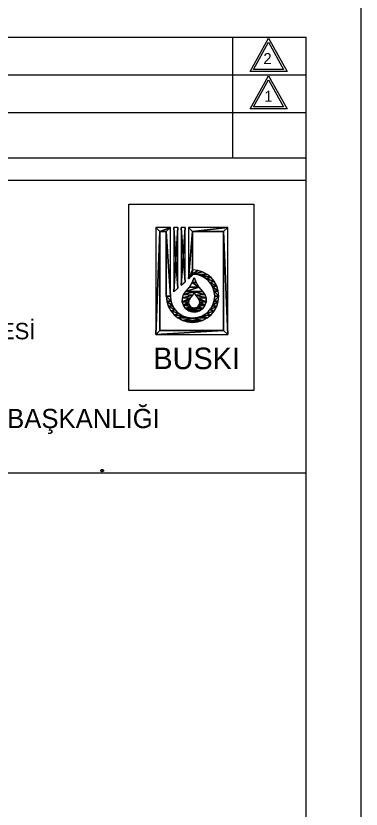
# Model space of a CAD drawing. Extents: x -10 to 1145, y -10 to 821.
# Drawn here: x 1082.1 to 1145, y 138.4 to 283.1 of the extents above; entities that cross this region are included whole.
import ezdxf

# ---------------------------------------------------------------- set-up
doc = ezdxf.new("R2010")
doc.units = 0
for name, color, linetype in [('Level 1', 7, 'Continuous'), ('Level 20', 7, 'Continuous'), ('Level 21', 7, 'Continuous'), ('Level 51', 7, 'Continuous'), ('Level 6', 7, 'Continuous'), ('Level 7', 7, 'Continuous'), ('Level 8', 7, 'Continuous')]:
    doc.layers.add(name, color=color, linetype=linetype)

msp = doc.modelspace()

# ---------------------------------------------------------------- linework, layer by layer
at = {"layer": 'Level 1'}
msp.add_lwpolyline([(1097.86, 200.4), (1097.9, 200.4), (1097.99, 200.36), (1098.03, 200.27), (1098.03, 200.1), (1097.94, 200.02), (1097.82, 199.97), (1097.69, 200.02), (1097.6, 200.1), (1097.6, 200.27), (1097.65, 200.36), (1097.73, 200.4), (1097.86, 200.4), (1097.99, 200.27), (1097.99, 200.14), (1097.9, 200.06), (1097.82, 199.97), (1097.9, 200.1), (1097.9, 200.31), (1097.86, 200.4)], dxfattribs=at)
msp.add_lwpolyline([(1097.86, 200.4), (1097.9, 200.4), (1097.99, 200.36), (1098.03, 200.27), (1098.03, 200.1), (1097.94, 200.02), (1097.82, 199.97), (1097.69, 200.02), (1097.6, 200.1), (1097.6, 200.27), (1097.65, 200.36), (1097.73, 200.4), (1097.86, 200.4), (1097.99, 200.27), (1097.99, 200.14), (1097.9, 200.06), (1097.82, 199.97), (1097.9, 200.1), (1097.9, 200.31), (1097.86, 200.4)], dxfattribs=at)
msp.add_lwpolyline([(1097.86, 200.4), (1097.9, 200.4), (1097.99, 200.36), (1098.03, 200.27), (1098.03, 200.1), (1097.94, 200.02), (1097.82, 199.97), (1097.69, 200.02), (1097.6, 200.1), (1097.6, 200.27), (1097.65, 200.36), (1097.73, 200.4), (1097.86, 200.4), (1097.99, 200.27), (1097.99, 200.14), (1097.9, 200.06), (1097.82, 199.97), (1097.9, 200.1), (1097.9, 200.31), (1097.86, 200.4)], dxfattribs=at)
msp.add_lwpolyline([(1097.86, 200.4), (1097.9, 200.4), (1097.99, 200.36), (1098.03, 200.27), (1098.03, 200.1), (1097.94, 200.02), (1097.82, 199.97), (1097.69, 200.02), (1097.6, 200.1), (1097.6, 200.27), (1097.65, 200.36), (1097.73, 200.4), (1097.86, 200.4), (1097.99, 200.27), (1097.99, 200.14), (1097.9, 200.06), (1097.82, 199.97), (1097.9, 200.1), (1097.9, 200.31), (1097.86, 200.4)], dxfattribs=at)
at = {"layer": 'Level 51'}
msp.add_lwpolyline([(-10, -10), (1145, -10), (1145, 821), (-10, 821)], close=True, dxfattribs=at)
at = {"layer": 'Level 6'}
for p, q in [((967.03, 279.24), (1135, 279.24)), ((967.03, 279.24), (1135, 279.24)), ((967.03, 279.24), (1135, 279.24)), ((967.03, 279.24), (1135, 279.24)), ((970.15, 279.24), (1131.87, 279.24)), ((970.15, 279.24), (1131.87, 279.24)), ((970.15, 279.24), (1131.87, 279.24)), ((970.15, 279.24), (1131.87, 279.24)), ((970.15, 279.24), (1131.87, 279.24)), ((970.15, 279.24), (1131.87, 279.24)), ((970.15, 279.24), (1131.87, 279.24)), ((970.15, 279.24), (1131.87, 279.24)), ((1121.62, 257.23), (1121.62, 279.24)), ((1121.62, 257.23), (1121.62, 279.24)), ((1121.62, 257.23), (1121.62, 279.24)), ((1121.62, 257.23), (1121.62, 279.24)), ((1135, 255.72), (1135, 279.24)), ((1135, 255.72), (1135, 279.24)), ((1135, 255.72), (1135, 279.24)), ((1135, 255.72), (1135, 279.24)), ((1135, 255.72), (1135, 279.24)), ((1135, 255.72), (1135, 279.24)), ((1135, 255.72), (1135, 279.24)), ((1135, 255.72), (1135, 279.24)), ((967.03, 272.38), (1135, 272.38)), ((967.03, 272.38), (1135, 272.38)), ((967.03, 272.38), (1135, 272.38)), ((967.03, 272.38), (1135, 272.38)), ((967.03, 265.52), (1135, 265.52)), ((967.03, 265.52), (1135, 265.52)), ((967.03, 265.52), (1135, 265.52)), ((967.03, 265.52), (1135, 265.52)), ((1135, 0), (1135, 262.93)), ((1135, 0), (1135, 262.93)), ((1135, 0), (1135, 262.93)), ((1135, 0), (1135, 262.93)), ((967.03, 257.23), (1135, 257.23)), ((967.03, 257.23), (1135, 257.23)), ((967.03, 257.23), (1135, 257.23)), ((967.03, 257.23), (1135, 257.23)), ((967.03, 253.14), (1135, 253.14)), ((967.03, 253.14), (1135, 253.14)), ((967.03, 253.14), (1135, 253.14)), ((967.03, 253.14), (1135, 253.14)), ((967.03, 199.78), (1135, 199.78)), ((967.03, 199.78), (1135, 199.78)), ((967.03, 199.78), (1135, 199.78)), ((967.03, 199.78), (1135, 199.78))]:
    msp.add_line(p, q, dxfattribs=at)
at = {"layer": 'Level 7'}
for points in [[(1124.76, 273), (1128.13, 279.05), (1131.5, 273)], [(1124.76, 273), (1128.13, 279.05), (1131.5, 273)], [(1124.76, 273), (1128.13, 279.05), (1131.5, 273)], [(1124.76, 273), (1128.13, 279.05), (1131.5, 273)], [(1125.38, 273.37), (1128.13, 278.3), (1130.88, 273.37)], [(1125.38, 273.37), (1128.13, 278.3), (1130.88, 273.37)], [(1125.38, 273.37), (1128.13, 278.3), (1130.88, 273.37)], [(1125.38, 273.37), (1128.13, 278.3), (1130.88, 273.37)], [(1124.76, 266.14), (1128.13, 272.19), (1131.5, 266.14)], [(1124.76, 266.14), (1128.13, 272.19), (1131.5, 266.14)], [(1124.76, 266.14), (1128.13, 272.19), (1131.5, 266.14)], [(1124.76, 266.14), (1128.13, 272.19), (1131.5, 266.14)], [(1125.38, 266.51), (1128.13, 271.44), (1130.88, 266.51)], [(1125.38, 266.51), (1128.13, 271.44), (1130.88, 266.51)], [(1125.38, 266.51), (1128.13, 271.44), (1130.88, 266.51)], [(1125.38, 266.51), (1128.13, 271.44), (1130.88, 266.51)]]:
    msp.add_lwpolyline(points, close=True, dxfattribs=at)
at = {"layer": 'Level 8'}
for points in [[(1102.65, 248.8), (1125.44, 248.8), (1125.44, 214.79), (1102.65, 214.79)], [(1107.58, 244.55), (1107.58, 225), (1108.34, 243.79)], [(1108.34, 243.79), (1110.26, 244.55), (1107.58, 244.55)], [(1107.58, 244.55), (1107.58, 225), (1108.34, 243.79)], [(1108.34, 243.79), (1110.26, 244.55), (1107.58, 244.55)], [(1110.26, 244.55), (1108.34, 243.79), (1109.5, 243.79)], [(1110.26, 244.55), (1108.34, 243.79), (1109.5, 243.79)], [(1110.26, 244.55), (1109.5, 243.79), (1110.26, 232)], [(1110.26, 244.55), (1109.5, 243.79), (1110.26, 232)], [(1111.23, 238.68), (1111.6, 244.55), (1110.85, 244.55)], [(1111.23, 238.68), (1110.85, 244.55), (1110.85, 232.82)], [(1111.23, 238.68), (1111.6, 244.55), (1110.85, 244.55)], [(1111.23, 238.68), (1110.85, 244.55), (1110.85, 232.82)], [(1111.23, 238.68), (1111.6, 233.46), (1111.6, 244.55)], [(1111.23, 238.68), (1111.6, 233.46), (1111.6, 244.55)], [(1112.57, 239.27), (1112.95, 244.55), (1112.19, 244.55)], [(1112.57, 239.27), (1112.19, 244.55), (1112.19, 233.99)], [(1112.57, 239.27), (1112.95, 244.55), (1112.19, 244.55)], [(1112.57, 239.27), (1112.19, 244.55), (1112.19, 233.99)], [(1112.57, 239.27), (1112.95, 234.63), (1112.95, 244.55)], [(1112.57, 239.27), (1112.95, 234.63), (1112.95, 244.55)], [(1113.53, 244.55), (1113.53, 235.15), (1114.29, 243.79)], [(1114.29, 243.79), (1120.71, 244.55), (1113.53, 244.55)], [(1113.53, 244.55), (1113.53, 235.15), (1114.29, 243.79)], [(1114.29, 243.79), (1120.71, 244.55), (1113.53, 244.55)], [(1120.71, 244.55), (1114.29, 243.79), (1119.95, 243.79)], [(1120.71, 244.55), (1114.29, 243.79), (1119.95, 243.79)], [(1120.71, 244.55), (1119.95, 243.79), (1120.71, 225)], [(1120.71, 244.55), (1119.95, 243.79), (1120.71, 225)], [(1108.34, 243.79), (1107.58, 225), (1108.34, 225.76)], [(1108.34, 243.79), (1107.58, 225), (1108.34, 225.76)], [(1109.5, 243.79), (1109.5, 232), (1110.26, 232)], [(1109.5, 243.79), (1109.5, 232), (1110.26, 232)], [(1114.29, 243.79), (1113.53, 235.15), (1114.29, 236.79)], [(1114.29, 243.79), (1113.53, 235.15), (1114.29, 236.79)], [(1119.95, 243.79), (1119.95, 225.76), (1120.71, 225)], [(1119.95, 243.79), (1119.95, 225.76), (1120.71, 225)], [(1112.57, 239.27), (1112.19, 233.99), (1112.95, 234.63)], [(1112.57, 239.27), (1112.19, 233.99), (1112.95, 234.63)], [(1111.23, 238.68), (1110.85, 232.82), (1111.6, 233.46)], [(1111.23, 238.68), (1110.85, 232.82), (1111.6, 233.46)], [(1114.29, 236.79), (1113.53, 235.15), (1114.29, 236.03)], [(1114.29, 236.79), (1113.53, 235.15), (1114.29, 236.03)], [(1114.29, 236.03), (1113.53, 235.15), (1114.29, 235.8)], [(1114.29, 236.03), (1113.53, 235.15), (1114.29, 235.8)], [(1114.29, 236.79), (1114.29, 236.03), (1115.22, 236.69)], [(1114.29, 236.79), (1114.29, 236.03), (1115.22, 236.69)], [(1115.22, 236.69), (1114.29, 236.03), (1116.12, 236.42)], [(1115.22, 236.69), (1114.29, 236.03), (1116.12, 236.42)], [(1116.12, 236.42), (1114.29, 236.03), (1116.95, 235.98)], [(1116.12, 236.42), (1114.29, 236.03), (1116.95, 235.98)], [(1114.29, 236.03), (1115.18, 235.93), (1116.95, 235.98)], [(1114.29, 236.03), (1115.18, 235.93), (1116.95, 235.98)], [(1116.95, 235.98), (1115.18, 235.93), (1117.67, 235.38)], [(1116.95, 235.98), (1115.18, 235.93), (1117.67, 235.38)], [(1115.18, 235.93), (1116.04, 235.63), (1117.67, 235.38)], [(1115.18, 235.93), (1116.04, 235.63), (1117.67, 235.38)], [(1114.22, 234.47), (1115.45, 233.62), (1113.71, 233.62)], [(1114.22, 234.47), (1115.45, 233.62), (1113.71, 233.62)], [(1114.58, 235.39), (1114.94, 234.47), (1114.22, 234.47)], [(1114.58, 235.39), (1114.94, 234.47), (1114.22, 234.47)], [(1114.94, 234.47), (1115.45, 233.62), (1114.22, 234.47)], [(1114.94, 234.47), (1115.45, 233.62), (1114.22, 234.47)], [(1116.04, 235.63), (1116.8, 235.15), (1117.67, 235.38)], [(1116.04, 235.63), (1116.8, 235.15), (1117.67, 235.38)], [(1117.67, 235.38), (1116.8, 235.15), (1118.27, 234.66)], [(1117.67, 235.38), (1116.8, 235.15), (1118.27, 234.66)], [(1116.8, 235.15), (1117.44, 234.51), (1118.27, 234.66)], [(1116.8, 235.15), (1117.44, 234.51), (1118.27, 234.66)], [(1118.27, 234.66), (1117.44, 234.51), (1118.71, 233.83)], [(1118.27, 234.66), (1117.44, 234.51), (1118.71, 233.83)], [(1117.44, 234.51), (1117.92, 233.75), (1118.71, 233.83)], [(1117.44, 234.51), (1117.92, 233.75), (1118.71, 233.83)], [(1115.45, 233.62), (1116.1, 232.88), (1113.06, 232.88)], [(1113.71, 233.62), (1115.45, 233.62), (1113.06, 232.88)], [(1115.45, 233.62), (1116.1, 232.88), (1113.06, 232.88)], [(1113.71, 233.62), (1115.45, 233.62), (1113.06, 232.88)], [(1118.71, 233.83), (1117.92, 233.75), (1118.98, 232.94)], [(1118.71, 233.83), (1117.92, 233.75), (1118.98, 232.94)], [(1117.92, 233.75), (1118.21, 232.9), (1118.98, 232.94)], [(1117.92, 233.75), (1118.21, 232.9), (1118.98, 232.94)], [(1118.98, 232.94), (1118.21, 232.9), (1119.07, 232)], [(1118.98, 232.94), (1118.21, 232.9), (1119.07, 232)], [(1109.5, 232), (1109.6, 231.07), (1110.36, 231.11)], [(1110.26, 232), (1109.5, 232), (1110.36, 231.11)], [(1109.5, 232), (1109.6, 231.07), (1110.36, 231.11)], [(1110.26, 232), (1109.5, 232), (1110.36, 231.11)], [(1112.43, 231.67), (1113.88, 231.65), (1112.42, 230.98)], [(1112.43, 231.67), (1113.88, 231.65), (1112.42, 230.98)], [(1113.88, 231.65), (1113.64, 231.32), (1112.42, 230.98)], [(1113.88, 231.65), (1113.64, 231.32), (1112.42, 230.98)], [(1112.65, 232.33), (1114.31, 232.16), (1112.43, 231.67)], [(1112.65, 232.33), (1114.31, 232.16), (1112.43, 231.67)], [(1114.31, 232.16), (1113.88, 231.65), (1112.43, 231.67)], [(1114.31, 232.16), (1113.88, 231.65), (1112.43, 231.67)], [(1113.06, 232.88), (1114.58, 232.76), (1112.65, 232.33)], [(1113.06, 232.88), (1114.58, 232.76), (1112.65, 232.33)], [(1114.58, 232.76), (1114.31, 232.16), (1112.65, 232.33)], [(1114.58, 232.76), (1114.31, 232.16), (1112.65, 232.33)], [(1116.1, 232.88), (1114.58, 232.76), (1113.06, 232.88)], [(1116.1, 232.88), (1114.58, 232.76), (1113.06, 232.88)], [(1116.1, 232.88), (1116.51, 232.33), (1114.58, 232.76)], [(1116.1, 232.88), (1116.51, 232.33), (1114.58, 232.76)], [(1114.58, 232.76), (1116.51, 232.33), (1114.85, 232.16)], [(1114.58, 232.76), (1116.51, 232.33), (1114.85, 232.16)], [(1116.51, 232.33), (1116.74, 231.67), (1114.85, 232.16)], [(1116.51, 232.33), (1116.74, 231.67), (1114.85, 232.16)], [(1114.85, 232.16), (1116.74, 231.67), (1115.28, 231.65)], [(1114.85, 232.16), (1116.74, 231.67), (1115.28, 231.65)], [(1116.74, 231.67), (1116.74, 230.98), (1115.28, 231.65)], [(1116.74, 231.67), (1116.74, 230.98), (1115.28, 231.65)], [(1115.28, 231.65), (1116.74, 230.98), (1115.52, 231.32)], [(1115.28, 231.65), (1116.74, 230.98), (1115.52, 231.32)], [(1118.21, 232.9), (1118.32, 232), (1119.07, 232)], [(1118.21, 232.9), (1118.32, 232), (1119.07, 232)], [(1119.07, 232), (1118.21, 231.11), (1118.98, 231.07)], [(1118.32, 232), (1118.21, 231.11), (1119.07, 232)], [(1119.07, 232), (1118.21, 231.11), (1118.98, 231.07)], [(1118.32, 232), (1118.21, 231.11), (1119.07, 232)], [(1110.36, 231.11), (1109.6, 231.07), (1110.66, 230.25)], [(1110.36, 231.11), (1109.6, 231.07), (1110.66, 230.25)], [(1109.6, 231.07), (1109.87, 230.17), (1110.66, 230.25)], [(1109.6, 231.07), (1109.87, 230.17), (1110.66, 230.25)], [(1110.66, 230.25), (1109.87, 230.17), (1111.14, 229.49)], [(1110.66, 230.25), (1109.87, 230.17), (1111.14, 229.49)], [(1109.87, 230.17), (1110.31, 229.34), (1111.14, 229.49)], [(1109.87, 230.17), (1110.31, 229.34), (1111.14, 229.49)], [(1113.64, 231.32), (1113.55, 230.92), (1112.42, 230.98)], [(1113.64, 231.32), (1113.55, 230.92), (1112.42, 230.98)], [(1112.42, 230.98), (1113.55, 230.92), (1112.62, 230.33)], [(1112.42, 230.98), (1113.55, 230.92), (1112.62, 230.33)], [(1113.55, 230.92), (1113.62, 230.52), (1112.62, 230.33)], [(1113.55, 230.92), (1113.62, 230.52), (1112.62, 230.33)], [(1113.62, 230.52), (1113.84, 230.17), (1112.62, 230.33)], [(1113.62, 230.52), (1113.84, 230.17), (1112.62, 230.33)], [(1112.62, 230.33), (1113.84, 230.17), (1113.03, 229.76)], [(1112.62, 230.33), (1113.84, 230.17), (1113.03, 229.76)], [(1113.84, 230.17), (1114.18, 229.94), (1113.03, 229.76)], [(1113.84, 230.17), (1114.18, 229.94), (1113.03, 229.76)], [(1115.32, 230.17), (1116.14, 229.76), (1114.98, 229.94)], [(1115.32, 230.17), (1116.14, 229.76), (1114.98, 229.94)], [(1115.54, 230.52), (1116.54, 230.33), (1115.32, 230.17)], [(1115.54, 230.52), (1116.54, 230.33), (1115.32, 230.17)], [(1116.54, 230.33), (1116.14, 229.76), (1115.32, 230.17)], [(1116.54, 230.33), (1116.14, 229.76), (1115.32, 230.17)], [(1115.52, 231.32), (1116.74, 230.98), (1115.61, 230.92)], [(1115.52, 231.32), (1116.74, 230.98), (1115.61, 230.92)], [(1115.61, 230.92), (1116.54, 230.33), (1115.54, 230.52)], [(1115.61, 230.92), (1116.54, 230.33), (1115.54, 230.52)], [(1116.74, 230.98), (1116.54, 230.33), (1115.61, 230.92)], [(1116.74, 230.98), (1116.54, 230.33), (1115.61, 230.92)], [(1117.92, 230.25), (1117.44, 229.49), (1118.71, 230.17)], [(1117.92, 230.25), (1117.44, 229.49), (1118.71, 230.17)], [(1118.71, 230.17), (1117.44, 229.49), (1118.27, 229.34)], [(1118.71, 230.17), (1117.44, 229.49), (1118.27, 229.34)], [(1118.21, 231.11), (1117.92, 230.25), (1118.98, 231.07)], [(1118.21, 231.11), (1117.92, 230.25), (1118.98, 231.07)], [(1118.98, 231.07), (1117.92, 230.25), (1118.71, 230.17)], [(1118.98, 231.07), (1117.92, 230.25), (1118.71, 230.17)], [(1111.14, 229.49), (1110.31, 229.34), (1111.78, 228.85)], [(1111.14, 229.49), (1110.31, 229.34), (1111.78, 228.85)], [(1110.31, 229.34), (1110.91, 228.62), (1111.78, 228.85)], [(1110.31, 229.34), (1110.91, 228.62), (1111.78, 228.85)], [(1111.78, 228.85), (1110.91, 228.62), (1112.54, 228.37)], [(1111.78, 228.85), (1110.91, 228.62), (1112.54, 228.37)], [(1110.91, 228.62), (1111.63, 228.02), (1112.54, 228.37)], [(1110.91, 228.62), (1111.63, 228.02), (1112.54, 228.37)], [(1114.18, 229.94), (1114.58, 229.86), (1113.03, 229.76)], [(1114.18, 229.94), (1114.58, 229.86), (1113.03, 229.76)], [(1114.58, 229.86), (1116.14, 229.76), (1113.03, 229.76)], [(1114.58, 229.86), (1116.14, 229.76), (1113.03, 229.76)], [(1113.03, 229.76), (1115.58, 229.36), (1113.58, 229.36)], [(1116.14, 229.76), (1115.58, 229.36), (1113.03, 229.76)], [(1113.03, 229.76), (1115.58, 229.36), (1113.58, 229.36)], [(1116.14, 229.76), (1115.58, 229.36), (1113.03, 229.76)], [(1113.58, 229.36), (1114.93, 229.14), (1114.24, 229.14)], [(1115.58, 229.36), (1114.93, 229.14), (1113.58, 229.36)], [(1113.58, 229.36), (1114.93, 229.14), (1114.24, 229.14)], [(1115.58, 229.36), (1114.93, 229.14), (1113.58, 229.36)], [(1114.98, 229.94), (1116.14, 229.76), (1114.58, 229.86)], [(1114.98, 229.94), (1116.14, 229.76), (1114.58, 229.86)], [(1116.8, 228.85), (1116.04, 228.37), (1117.67, 228.62)], [(1116.8, 228.85), (1116.04, 228.37), (1117.67, 228.62)], [(1117.67, 228.62), (1116.04, 228.37), (1116.95, 228.02)], [(1117.67, 228.62), (1116.04, 228.37), (1116.95, 228.02)], [(1117.44, 229.49), (1116.8, 228.85), (1118.27, 229.34)], [(1117.44, 229.49), (1116.8, 228.85), (1118.27, 229.34)], [(1118.27, 229.34), (1116.8, 228.85), (1117.67, 228.62)], [(1118.27, 229.34), (1116.8, 228.85), (1117.67, 228.62)], [(1112.54, 228.37), (1111.63, 228.02), (1113.39, 228.08)], [(1112.54, 228.37), (1111.63, 228.02), (1113.39, 228.08)], [(1113.39, 228.08), (1111.63, 228.02), (1114.29, 227.98)], [(1113.39, 228.08), (1111.63, 228.02), (1114.29, 227.98)], [(1111.63, 228.02), (1112.46, 227.58), (1114.29, 227.98)], [(1111.63, 228.02), (1112.46, 227.58), (1114.29, 227.98)], [(1114.29, 227.98), (1112.46, 227.58), (1116.12, 227.58)], [(1114.29, 227.98), (1112.46, 227.58), (1116.12, 227.58)], [(1112.46, 227.58), (1113.36, 227.31), (1115.22, 227.31)], [(1116.12, 227.58), (1112.46, 227.58), (1115.22, 227.31)], [(1112.46, 227.58), (1113.36, 227.31), (1115.22, 227.31)], [(1116.12, 227.58), (1112.46, 227.58), (1115.22, 227.31)], [(1115.22, 227.31), (1113.36, 227.31), (1114.29, 227.22)], [(1115.22, 227.31), (1113.36, 227.31), (1114.29, 227.22)], [(1115.18, 228.08), (1114.29, 227.98), (1116.95, 228.02)], [(1115.18, 228.08), (1114.29, 227.98), (1116.95, 228.02)], [(1116.95, 228.02), (1114.29, 227.98), (1116.12, 227.58)], [(1116.95, 228.02), (1114.29, 227.98), (1116.12, 227.58)], [(1116.04, 228.37), (1115.18, 228.08), (1116.95, 228.02)], [(1116.04, 228.37), (1115.18, 228.08), (1116.95, 228.02)], [(1119.95, 225.76), (1107.58, 225), (1120.71, 225)], [(1107.58, 225), (1119.95, 225.76), (1108.34, 225.76)], [(1119.95, 225.76), (1107.58, 225), (1120.71, 225)], [(1107.58, 225), (1119.95, 225.76), (1108.34, 225.76)]]:
    msp.add_lwpolyline(points, close=True, dxfattribs=at)
for points in [[(1110.26, 232), (1110.26, 232), (1110.26, 244.55), (1107.58, 244.55), (1107.58, 225), (1120.71, 225), (1120.71, 244.55), (1113.53, 244.55), (1113.53, 235.15), (1114.29, 235.8), (1114.29, 236.03)], [(1110.26, 232), (1110.26, 232), (1110.26, 244.55), (1107.58, 244.55), (1107.58, 225), (1120.71, 225), (1120.71, 244.55), (1113.53, 244.55), (1113.53, 235.15), (1114.29, 235.8), (1114.29, 236.03)], [(1111.6, 244.55), (1110.85, 244.55), (1110.85, 232.82), (1111.6, 233.46), (1111.6, 244.55)], [(1111.6, 244.55), (1110.85, 244.55), (1110.85, 232.82), (1111.6, 233.46), (1111.6, 244.55)], [(1112.19, 233.99), (1112.95, 234.63), (1112.95, 244.55), (1112.19, 244.55), (1112.19, 233.99)], [(1112.19, 233.99), (1112.95, 234.63), (1112.95, 244.55), (1112.19, 244.55), (1112.19, 233.99)], [(1109.51, 232), (1109.5, 232), (1109.5, 243.79), (1108.34, 243.79), (1108.34, 225.76), (1119.95, 225.76), (1119.95, 243.79), (1114.29, 243.79), (1114.29, 236.79)], [(1109.51, 232), (1109.5, 232), (1109.5, 243.79), (1108.34, 243.79), (1108.34, 225.76), (1119.95, 225.76), (1119.95, 243.79), (1114.29, 243.79), (1114.29, 236.79)], [(1114.29, 236.79), (1114.29, 236.78)], [(1114.29, 236.79), (1114.29, 236.78)], [(1114.29, 236.03), (1114.29, 236.03)], [(1114.29, 236.03), (1114.29, 236.03)]]:
    msp.add_lwpolyline(points, dxfattribs=at)
for centre, radius, start, end in [((1114.29, 232), 4.78, 180, 90), ((1114.29, 232), 4.78, 180, 90), ((1114.29, 232), 4.03, 180, 90), ((1114.29, 232), 4.03, 180, 90), ((1108.99, 237.05), 5.83, 314.2894, 343.392), ((1108.99, 237.05), 5.83, 314.2894, 343.392), ((1120.17, 237.05), 5.83, 196.608, 225.7106), ((1120.17, 237.05), 5.83, 196.608, 225.7106), ((1114.58, 231.3), 2.19, 133.9191, 46.0809), ((1114.58, 231.3), 2.19, 133.9191, 46.0809), ((1114.58, 230.89), 1.03, 132.7094, 47.2906), ((1114.58, 230.89), 1.03, 132.7094, 47.2906), ((1112.34, 233.4), 2.33, 311.4103, 344.0384), ((1112.34, 233.4), 2.33, 311.4103, 344.0384), ((1116.82, 233.4), 2.33, 195.9616, 228.5897), ((1116.82, 233.4), 2.33, 195.9616, 228.5897)]:
    msp.add_arc(centre, radius, start, end, dxfattribs=at)

# ---------------------------------------------------------------- texts
at = {"layer": 'Level 1'}
for s, p in [('2', (1127.2, 274.33)), ('1', (1127.37, 267.46))]:
    msp.add_text(s, height=2, dxfattribs=at).set_placement(p)
at = {"layer": 'Level 20'}
msp.add_text('PLANLAMA YATIRIM VE İNŞAAT DAİRE BAŞKANLIĞI', height=3.5, dxfattribs=at).set_placement((992.59, 207.94))
at = {"layer": 'Level 21'}
msp.add_text('BUSKI', height=3.926, dxfattribs=at).set_placement((1107.15, 218.69))
msp.add_text('BUSKI', height=3.926, dxfattribs=at).set_placement((1107.15, 218.69))
at = {"layer": 'Level 7'}
msp.add_text('BURSA SU VE KANALİZASYON İDARESİ', height=3, dxfattribs=at).set_placement((1009.64, 224.13))

doc.saveas('drawing.dxf')
